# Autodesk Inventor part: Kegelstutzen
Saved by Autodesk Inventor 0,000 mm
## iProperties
Created: 2010-12
Part Number: Kegelstutzen
Material: Standard
Document SubType Name: Blech
Designer: mmic
Density: 1 g/cm^3
Sheet Metal Rule: Standard_mm
Sheet Metal Width: 0,000 mm
Sheet Metal Length: 0,000 mm^2
Author: mmic
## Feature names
1. Umdrehung1 [Revolution]
2. Extrusion1
3. Extrusion3
